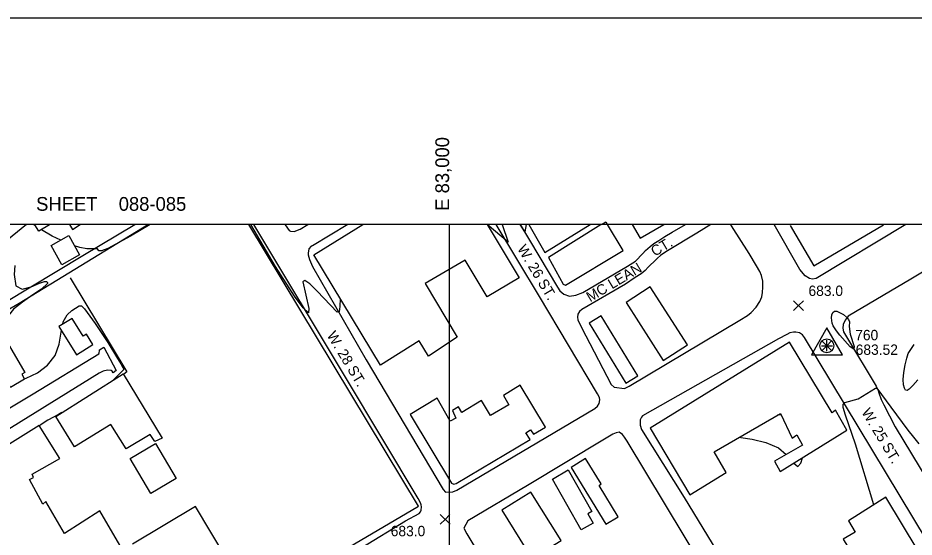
# Model space of a CAD drawing. Extents: x 79600 to 91800, y 75600 to 84400.
# Drawn here: x 82374 to 83676, y 83546 to 84300 of the extents above; entities that cross this region are included whole.
import ezdxf

# ---------------------------------------------------------------- set-up
doc = ezdxf.new("R2010")
doc.units = 0
for name, color, linetype in [('084-085$0$BLDG', 7, 'Continuous'), ('084-085$0$GRID', 7, 'Continuous'), ('084-085$0$INTER', 7, 'Continuous'), ('084-085$0$RECREATION', 7, 'Continuous'), ('084-085$0$ROAD', 7, 'Continuous'), ('084-085$0$ROAD-NAME', 7, 'Continuous'), ('084-085$0$SPOTMARK', 7, 'Continuous'), ('084-085$0$SPOTS', 7, 'Continuous'), ('084-085$0$TI_BORDER', 7, 'Continuous'), ('084-085$0$TI_HOR', 7, 'Continuous'), ('084-085$0$TI_SHEET', 7, 'Continuous'), ('084-085$0$TI_VER', 7, 'Continuous')]:
    doc.layers.add(name, color=color, linetype=linetype)

# ---------------------------------------------------------------- blocks, each defined once
blk = doc.blocks.new('084-085$0$SPOTX')
at = {"layer": '084-085$0$SPOTMARK'}
for p, q in [((-0.37, 0.358), (0.351, -0.358)), ((-0.012, 0), (-0.37, -0.358)), ((-0.012, 0), (0.347, 0.358))]:
    blk.add_line(p, q, dxfattribs=at)
blk = doc.blocks.new('084-085$0$VCP')
for p, q in [((-0.37, 0.347), (0.351, -0.37)), ((-0.012, -0.012), (0.347, 0.347)), ((-0.012, -0.012), (-0.37, -0.37))]:
    blk.add_line(p, q)
blk.add_circle((0, -0.012), 0.505)
blk = doc.blocks.new('084-085$0$HVP')
for p, q in [((-0.4, 0), (0.4, 0)), ((0, -0.4), (0, 0.4))]:
    blk.add_line(p, q)
blk.add_lwpolyline([(0, 1.3), (-1.126, -0.65), (1.126, -0.65)], close=True)

msp = doc.modelspace()

# ---------------------------------------------------------------- linework, layer by layer
at = {"layer": '084-085$0$BLDG'}
for p, q in [((82403.8, 83990.2), (82398, 83999.7)), ((82419.6, 83999.7), (82403.8, 83990.2)), ((83220.9, 84000), (83144.5, 83952.4))]:
    msp.add_line(p, q, dxfattribs=at)
for points in [[(83221.5, 84000.3), (83227.6, 84004.1), (83230.2, 83999.5)], [(82448.3, 84000.3), (82452.8, 83992.8), (82463.9, 83999.9)], [(82900.5, 83796), (82803.5, 83956.1), (82874.6, 84000)], [(83055.1, 84000), (83101.6, 83922.6), (83055.3, 83895.2), (83023.4, 83948.4), (82965.2, 83914.4), (83011.7, 83836.5), (82969.9, 83809.2), (82956.4, 83831), (82900.5, 83796)], [(83115.7, 84000), (83139.2, 83959.3), (83205, 84000)], [(83144.5, 83952.4), (83165.6, 83913.3), (83169, 83912), (83253, 83962.6), (83230.2, 84000)], [(83265.8, 84000), (83277.6, 83980.3), (83311.9, 84000)], [(83495.5, 83998.6), (83529.7, 83940.2), (83631.2, 83999.7)], [(82528.6, 83523.1), (82492.4, 83584.5), (82441.2, 83551.6), (82414, 83597.9), (82409.8, 83594.2), (82390.3, 83629.8), (82396.1, 83632.8), (82394.2, 83637.6), (82434.3, 83660.4), (82404.6, 83708.4), (82303, 83645.3)], [(82701.2, 83474.1), (82631.4, 83590.5), (82540.2, 83535.8)]]:
    msp.add_lwpolyline(points, dxfattribs=at)
for points in [[(82447.4, 83984.1), (82463.1, 83956.2), (82437.4, 83941.8), (82421.7, 83969.6)], [(83311, 83802.9), (83346.3, 83825.6), (83292.3, 83909.7), (83257, 83887)], [(82458.7, 83810.9), (82482.4, 83825.7), (82473.1, 83840.7), (82468.4, 83837.8), (82452.2, 83863.7), (82433.2, 83851.8)], [(83274.1, 83780.4), (83221.1, 83867.4), (83203.5, 83856.7), (83256.6, 83769.7)], [(82341.8, 83855.9), (82383.7, 83785.4), (82379.2, 83782.6), (82383.3, 83775.8), (82362.7, 83763.7), (82359.1, 83770.2), (82354, 83767.2), (82327.1, 83811.2), (82286.1, 83787), (82316.7, 83735.4), (82297.5, 83724.1), (82293, 83732), (82282.9, 83727.1), (82287, 83719.8), (82270.6, 83711.2), (82263.3, 83725.1), (82255.9, 83721), (82225.8, 83773.1), (82248.6, 83783.9), (82237.6, 83802.7), (82266.8, 83818.9), (82269.3, 83814.5)], [(83481.2, 83641.4), (83577.9, 83701.4), (83561.4, 83730.7), (83556.6, 83726.7), (83494.7, 83829.3), (83292.1, 83704.4), (83349.7, 83607.6), (83402.4, 83640.1), (83385.3, 83669.9), (83481.3, 83725.8), (83498.5, 83689.7), (83505.1, 83694.7), (83513.5, 83680), (83472.9, 83656.7)], [(82565.6, 83695.3), (82530.7, 83674.2), (82508.4, 83709.7), (82455.9, 83677.2), (82428.8, 83721.5), (82526.6, 83783.2), (82582.9, 83690), (82572.5, 83685.2)], [(82943.5, 83724.4), (83003.7, 83624.5), (83007.1, 83623.3), (83010.1, 83624.1), (83118, 83687.9), (83111.6, 83697.7), (83118.3, 83702.1), (83122.7, 83695.6), (83139.9, 83706.1), (83103.1, 83767), (83078.8, 83751.9), (83086.8, 83738.2), (83060.1, 83723), (83047.1, 83744.5), (83018.4, 83727.2), (83013.4, 83735.3), (83004.7, 83730.1), (83009.9, 83719.1), (83001.4, 83714.7), (82982.6, 83747.8)], [(82573.4, 83682.4), (82603.6, 83631.4), (82566.5, 83609.5), (82536.4, 83660.5)], [(83245.7, 83575.9), (83217.8, 83621.4), (83221.1, 83623.4), (83198.3, 83660.5), (83177.1, 83647.5), (83227.8, 83565)], [(83201.4, 83580.1), (83209.1, 83566.7), (83192, 83557), (83150, 83630.6), (83173.1, 83643.8), (83207.4, 83583.5)], [(83162.6, 83541.3), (83118.9, 83611.7), (83076.5, 83585.4), (83120.2, 83515)], [(83656, 83409.3), (83727, 83450.9), (83634.6, 83604.4), (83580.1, 83570), (83590.1, 83553.4), (83572.3, 83543.1), (83584.4, 83523.6), (83564.8, 83510.7), (83586.1, 83474.4), (83611.1, 83486.7), (83630.9, 83451.6), (83623.5, 83447.6), (83631.3, 83431.8), (83639.7, 83436.4)]]:
    msp.add_lwpolyline(points, close=True, dxfattribs=at)
at = {"layer": '084-085$0$GRID'}
for p, q in [((85000, 84000), (80000, 84000)), ((83000, 84000), (83000, 80000))]:
    msp.add_line(p, q, dxfattribs=at)
at = {"layer": '084-085$0$INTER'}
for p, q in [((82385.8, 84000), (82352, 83972.7)), ((82399.1, 83998), (82395.8, 84000))]:
    msp.add_line(p, q, dxfattribs=at)
for points in [[(82435.8, 83977.5), (82423.2, 83983.2), (82407.8, 83992.6)], [(82565.7, 84000), (82537.3, 83983.4), (82504.2, 83965.4), (82495.2, 83962), (82491.2, 83961.9), (82489.1, 83964.6), (82473.8, 83964.8), (82463.7, 83966.5), (82455.7, 83969.2)], [(82841.9, 83892.8), (82841.4, 83881.3), (82840.4, 83873.5), (82837.5, 83872.8), (82808.4, 83903.1), (82797.5, 83913.9), (82790.4, 83918.7), (82787.6, 83916.7), (82796.2, 83878.2), (82795.6, 83871.8), (82787.9, 83878.9), (82775.2, 83896.2), (82747.6, 83939.2), (82712.1, 84000)], [(83077, 84000), (83086, 83974.5), (83055.2, 84000)], [(83112, 84000), (83110.2, 83989.3), (83103.3, 84000)], [(82369, 83940.8), (82368.3, 83927.6), (82370.4, 83911), (82379.6, 83906), (82392.7, 83909.4), (82404.7, 83915), (82412, 83917.6), (82415.2, 83917.4), (82416.4, 83916), (82416.7, 83914.4), (82407.9, 83906.4), (82395.3, 83898), (82380.2, 83887.5), (82367.3, 83877), (82359.9, 83867.8), (82356.3, 83860.8), (82353.5, 83856.4), (82344.1, 83854.9), (82342.2, 83855.1)], [(82438.7, 83855.3), (82439.4, 83858.7), (82445, 83869), (82451.9, 83875.4), (82462.3, 83881.8), (82465.7, 83881.8), (82470.2, 83877.8), (82485.8, 83856.6), (82504, 83828.7), (82518.4, 83805.4), (82523.2, 83797.7), (82526.1, 83792.5), (82527.2, 83789.4), (82512, 83774)], [(82383.1, 83776.2), (82385.4, 83777), (82402.1, 83785), (82416.7, 83795.9), (82427.5, 83809.9), (82433.3, 83826.6), (82436.2, 83843.9), (82436.7, 83846.1)], [(83680.9, 83774.6), (83673.6, 83766.2), (83668.6, 83761.1), (83665.4, 83759.1), (83663.2, 83759.7), (83661.4, 83762.3), (83660.2, 83767.3), (83659.9, 83775), (83660.8, 83785.4), (83662.6, 83796.5), (83664.9, 83806.2), (83667.1, 83812.8), (83675.7, 83825.9)], [(83616.9, 83593.3), (83590.2, 83681.4), (83575.9, 83723.5), (83572.4, 83734.5), (83572.5, 83738.8), (83574.8, 83741.9), (83594.1, 83747), (83619.3, 83762.6), (83621.6, 83762.5), (83641.6, 83734.8), (83666.3, 83701.7), (83674.5, 83691.2), (83682.3, 83681.9)], [(82437.5, 83727), (82432.6, 83724.5), (82417.1, 83716.1), (82405.9, 83708.7), (82405, 83707.7)], [(83482.3, 83723.8), (83479.4, 83723.7), (83476.9, 83723.2)], [(83421.8, 83691.2), (83423.7, 83691), (83440.1, 83688.5), (83460, 83683.8), (83478.5, 83675.7), (83489.6, 83666.3)], [(83500.9, 83653.6), (83506.7, 83649), (83511.2, 83653.6), (83513.4, 83661.4)]]:
    msp.add_lwpolyline(points, dxfattribs=at)
msp.add_lwpolyline([(83577.5, 83865.6), (83580.2, 83862), (83581.5, 83858.6), (83581.4, 83852.1), (83582.6, 83841.1), (83588.3, 83823.1), (83588, 83819.1), (83582.8, 83822.5), (83567.5, 83839.5), (83562.8, 83845.7), (83558.2, 83852.9), (83556.5, 83857), (83555.5, 83864.7), (83555.9, 83868.8), (83557.3, 83872.2), (83559.8, 83874.2), (83563.5, 83874.4), (83573.2, 83869.4)], close=True, dxfattribs=at)
at = {"layer": '084-085$0$RECREATION'}
for points in [[(82721.9, 83461.4), (82788.6, 83492.9), (82955.4, 83591.4), (82709.2, 84000)], [(82449.4, 83922.9), (82531.9, 83786), (82527.4, 83782.7)]]:
    msp.add_lwpolyline(points, dxfattribs=at)
at = {"layer": '084-085$0$ROAD'}
for points in [[(82017.7, 83109.7), (82472.9, 83327.6), (82725.1, 83448.6), (82751.9, 83462.2), (82775.3, 83473.8), (82803.1, 83489.2), (82832.5, 83506.1), (82873.2, 83531), (82936.7, 83569.8), (82956.3, 83580.7), (82958.4, 83583), (82959.5, 83585.5), (82959.8, 83590.2), (82959.4, 83593.2), (82958.5, 83595.9), (82955.2, 83602.5), (82851, 83776.1), (82716.1, 84000)], [(82304.1, 83999.9), (82263.6, 83976.1), (82191.9, 83932.1), (82148.7, 83905.2), (82132.9, 83894.1), (82131.7, 83892.8), (82129.5, 83888.1), (82130, 83883.9), (82181.1, 83798.6), (82183.1, 83794.7), (82193.2, 83792.1), (82197.9, 83793.6), (82202.8, 83796.1), (82468, 83955), (82543.3, 84000)], [(82563.4, 84000), (82375.3, 83885.5), (82204.3, 83785.7)], [(82761.8, 83999.6), (82767.4, 83991.4), (82769.4, 83990.3), (82775, 83990), (82783.6, 83993.3), (82794.6, 84000)], [(82852.9, 84000), (82801.6, 83969.3), (82799.4, 83968.7), (82796, 83964.6), (82795.1, 83958.6), (82795.3, 83955.9), (82797, 83949.4), (82801.6, 83939), (82879.3, 83803.5), (82991.3, 83615.6), (82994.6, 83611.6), (83005.2, 83611.8), (83011.4, 83614.6), (83211.7, 83733.1), (83215.4, 83736.3), (83218.2, 83740.2), (83219.1, 83745.6), (83218.3, 83749), (83215.7, 83754.3), (83131.5, 83895.6), (83068.6, 84000)], [(83103.2, 84000), (83157.4, 83909.2), (83161, 83903.8), (83166.6, 83898.9), (83174.7, 83896.1), (83184, 83897.3), (83194.3, 83901.5), (83259.3, 83939.4), (83270.8, 83947), (83281.5, 83957.9), (83285.5, 83962.4), (83292, 83968.2), (83297.5, 83972.3), (83304.7, 83977), (83313.2, 83982.5), (83324.2, 83988.8), (83343.4, 84000)], [(83380.4, 84000), (83360.1, 83987.6), (83317.2, 83961.7), (83313.3, 83959.4), (83307.3, 83955), (83302.6, 83951.4), (83297.9, 83946.2), (83292.1, 83941), (83289.4, 83938.1), (83284.7, 83933.1), (83279.2, 83928.7), (83270.5, 83923), (83256.1, 83913.4), (83193, 83876.8), (83189.6, 83873.8), (83187.2, 83869.9), (83186.6, 83865.4), (83187.2, 83861.5), (83192.4, 83850.7), (83235.5, 83767.9), (83239.8, 83763.9), (83254.9, 83762.2), (83261.4, 83765.5), (83422.6, 83861.3), (83433.5, 83867.8), (83438.7, 83872.2), (83446, 83880), (83451.2, 83888.2), (83454.1, 83895.3), (83455.5, 83901.6), (83455.9, 83909.1), (83455.7, 83917.7), (83453.9, 83926.2), (83451.2, 83931.8), (83446.5, 83940), (83435.8, 83958)], [(83435.8, 83958), (83410.1, 83998.1), (83408.2, 84000)], [(83663.7, 84000), (83533.1, 83921.7), (83528, 83920.9), (83523.5, 83921.5), (83517.2, 83925.5), (83509.5, 83934.8), (83472.4, 84000)], [(83802.8, 84000), (83670.7, 83920.7), (83579.8, 83866.8), (83575.3, 83861), (83572.7, 83854.8), (83572.1, 83849.7), (83573.2, 83844.5), (83577.5, 83837.1), (83620.4, 83765.2), (83623.4, 83758.9), (83624.3, 83755.5), (83627.8, 83746.3), (83631.4, 83738.3), (83647.8, 83706.6), (83754.2, 83531)], [(83773.1, 83410.5), (83516.2, 83836.1), (83513.2, 83839.8), (83508.9, 83842.9), (83503.9, 83844), (83500.5, 83843.9), (83495.2, 83843), (83490.8, 83840.6), (83478.4, 83834.3), (83280.9, 83722.2), (83279.5, 83720.6), (83277.5, 83716.4), (83277.4, 83712.9), (83277.7, 83708.8), (83279.6, 83702.6), (83341.4, 83603.8), (83437.8, 83445.5), (83557.9, 83246.8), (83560.8, 83244.2), (83563.2, 83243.4), (83566.6, 83243.6), (83575.9, 83247.5), (83737, 83345.9)], [(82274.2, 83681.5), (82395.7, 83754.4), (82491.2, 83812.5), (82491.8, 83813.6), (82492.2, 83816.6), (82492.2, 83818), (82498.4, 83822.1), (82516.5, 83788.3), (82511.9, 83785), (82510.6, 83787.3), (82509.2, 83788.1), (82503.7, 83788.5), (82497.4, 83787.1), (82491.6, 83784.2), (82191.7, 83599)]]:
    msp.add_lwpolyline(points, dxfattribs=at)
msp.add_lwpolyline([(83258.9, 83685.5), (83255, 83691.4), (83251.9, 83695.4), (83247.2, 83698.4), (83242.7, 83697.9), (83238, 83695.8), (83225.9, 83688.7), (83113.8, 83621.3), (83027.1, 83570.1), (83021.2, 83559.2), (83025.9, 83551), (83103.6, 83421.6), (83153.7, 83339.9), (83156.8, 83338.2), (83161.9, 83337.7), (83167, 83339.8), (83383.6, 83467.4), (83386.4, 83469.6), (83386.7, 83472.2), (83385.9, 83475.5), (83368.8, 83503.1)], close=True, dxfattribs=at)
at = {"layer": '084-085$0$TI_BORDER'}
msp.add_lwpolyline([(79700, 84300), (86700, 84300), (86700, 79700), (79700, 79700)], close=True, dxfattribs=at)
at = {"layer": '084-085$0$TI_HOR'}
for p, q in [((83540.9, 83824.1), (83556.9, 83824.1)), ((83548.9, 83816.1), (83548.9, 83832))]:
    msp.add_line(p, q, dxfattribs=at)

# ---------------------------------------------------------------- block references
at = {"layer": '084-085$0$SPOTS', "xscale": 20, "yscale": 20}
for p in [(83507.9, 83882.3), (82994.3, 83572)]:
    msp.add_blockref('084-085$0$SPOTX', p, dxfattribs=at)
at = {"layer": '084-085$0$TI_HOR', "xscale": 20, "yscale": 20}
msp.add_blockref('084-085$0$HVP', (83548.9, 83824.1), dxfattribs=at)
at = {"layer": '084-085$0$TI_VER', "xscale": 20, "yscale": 20}
msp.add_blockref('084-085$0$VCP', (83548.8, 83824.1), dxfattribs=at)

# ---------------------------------------------------------------- texts
at = {"layer": '084-085$0$GRID'}
msp.add_text('E 83,000', height=20, rotation=90, dxfattribs=at).set_placement((83000, 84020))
at = {"layer": '084-085$0$ROAD-NAME'}
for s, rotation, p in [('CT.', 30.8439, (83298.8, 83953.2)), ('W. 26 ST.', 300.8831, (83098.5, 83965.2)), ('MC LEAN', 30.8439, (83205, 83887)), ('W. 28 ST.', 300.8831, (82821.8, 83839.5)), ('W. 25 ST.', 300.8831, (83598.5, 83727.8))]:
    msp.add_text(s, height=15, rotation=rotation, dxfattribs=at).set_placement(p)
at = {"layer": '084-085$0$SPOTS'}
for p in [(83522.1, 83896.4), (82915.2, 83547.6)]:
    msp.add_text('683.0', height=15, dxfattribs=at).set_placement(p)
at = {"layer": '084-085$0$TI_HOR'}
msp.add_text('760', height=15, dxfattribs=at).set_placement((83590, 83832.1))
at = {"layer": '084-085$0$TI_SHEET'}
for s, p in [('SHEET', (82400, 84020)), ('088-085', (82520, 84020))]:
    msp.add_text(s, height=20, dxfattribs=at).set_placement(p)
at = {"layer": '084-085$0$TI_VER'}
msp.add_text('683.52', height=15, dxfattribs=at).set_placement((83590.7, 83810.9))

doc.saveas('drawing.dxf')
